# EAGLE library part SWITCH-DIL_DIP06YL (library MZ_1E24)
DIL/CODE SWITCH
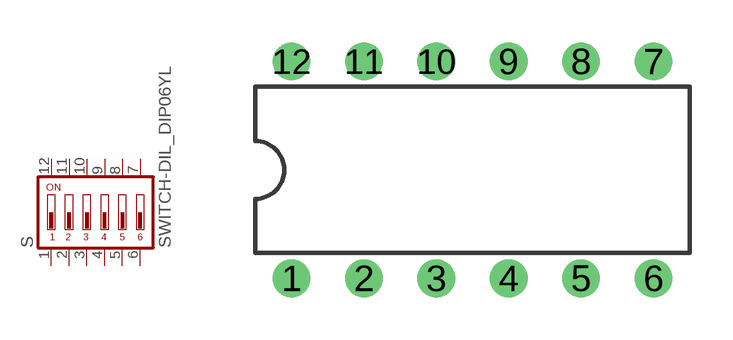
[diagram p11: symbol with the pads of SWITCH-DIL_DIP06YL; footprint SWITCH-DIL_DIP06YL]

Designator prefix S

## SWITCH-DIL_DIP06YL  [SWITCH-DIL_DIP06YL]
1  1  pas
2  2  pas
3  3  pas
4  4  pas
5  5  pas
6  6  pas
7  7  pas
8  8  pas
9  9  pas
10  10  pas
11  11  pas
12  12  pas

## Footprint SWITCH-DIL_DIP06YL (pad centres in mm)
DIL/CODE SWITCH
drill 0.813 round: 1 -6.35,-3.81; 2 -3.81,-3.81; 3 -1.27,-3.81; 4 1.27,-3.81; 5 3.81,-3.81; 6 6.35,-3.81; 7 6.35,3.81; 8 3.81,3.81; 9 1.27,3.81; 10 -1.27,3.81; 11 -3.81,3.81; 12 -6.35,3.81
